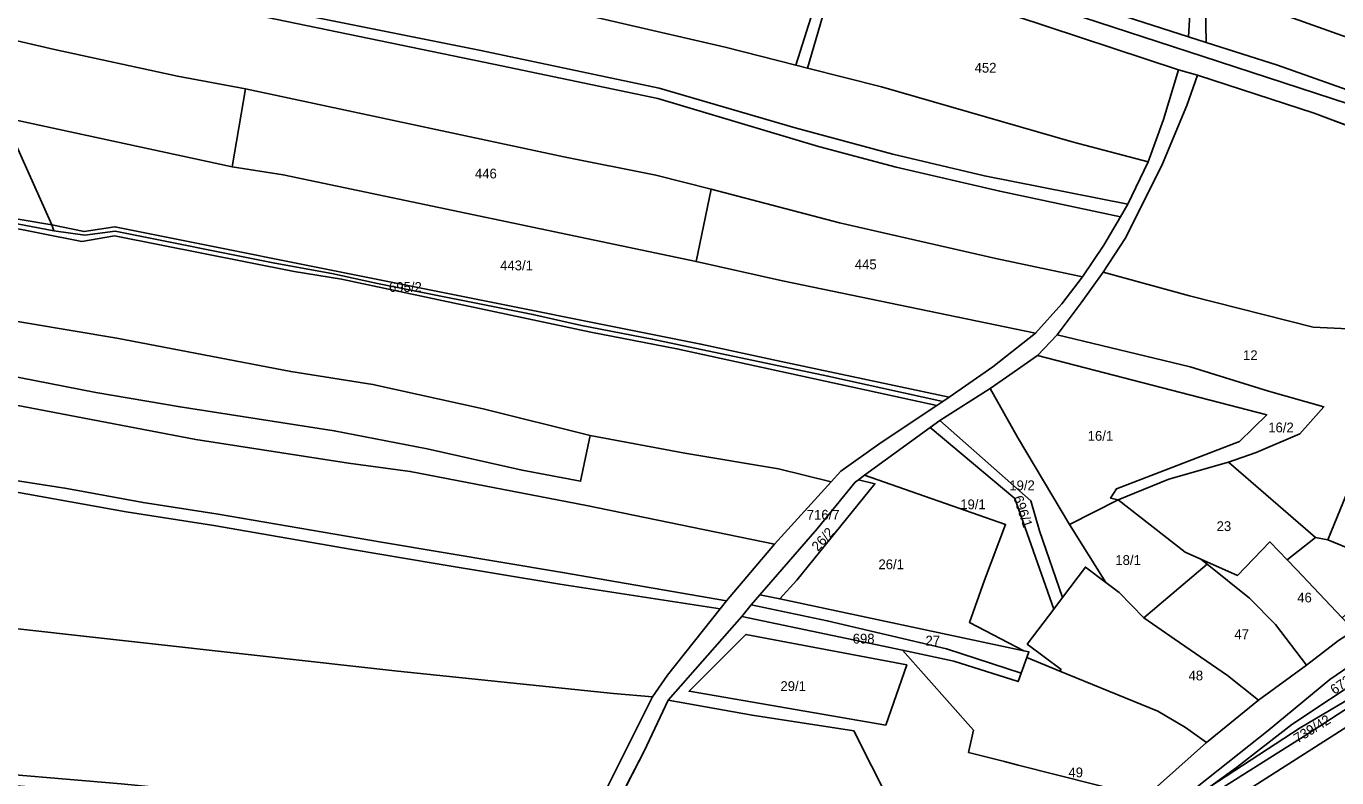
# Model space of a CAD drawing. Extents: x -629983 to -626385, y -1072828 to -1067897.
# Drawn here: x -627674 to -627272.2, y -1070260.1 to -1070029.7 of the extents above; entities that cross this region are included whole.
import ezdxf

# ---------------------------------------------------------------- set-up
doc = ezdxf.new("R2010")
doc.units = 0
for name, color, linetype in [('Parcela nároku', 7, 'Continuous'), ('Parcelní číslo', 7, 'Continuous'), ('Plocha PÚ', 7, 'Continuous'), ('silnice III třídy', 7, 'Continuous'), ('Vnitřní obvod_šetřený', 7, 'Continuous')]:
    doc.layers.add(name, color=color, linetype=linetype)

msp = doc.modelspace()

# ---------------------------------------------------------------- linework, layer by layer
at = {"layer": 'Parcela nároku'}
for points in [[(-627966.68, -1069918.48), (-627860.41, -1069943.87), (-627798.46, -1069959.34), (-627761.08, -1069969.25), (-627698.9, -1069984.16), (-627525.35, -1070020.94), (-627459.67, -1070036.19), (-627438.03, -1070041.67), (-627433.43, -1070027.14), (-627428.85, -1070009.96), (-627472.67, -1069998.76), (-627548.5, -1069979.01), (-627683.65, -1069947.01), (-627730.62, -1069934.75), (-627791.94, -1069919.96), (-627822.96, -1069911.43), (-627871.54, -1069899.35), (-627908.74, -1069890.74), (-627953.38, -1069880.27)], [(-627966.68, -1069918.48), (-627860.41, -1069943.87), (-627798.46, -1069959.34), (-627761.08, -1069969.25), (-627698.9, -1069984.16), (-627525.35, -1070020.94), (-627459.67, -1070036.19), (-627438.03, -1070041.67), (-627434.5, -1070042.56), (-627411.76, -1070048.32), (-627353.35, -1070065.17), (-627330, -1070071.29), (-627336.22, -1070084.29), (-627380.22, -1070075.61), (-627408.28, -1070068.97), (-627438.24, -1070060.91), (-627479.97, -1070048.75), (-627534.6, -1070037.2), (-627642.99, -1070015.46), (-627734.04, -1069994.19), (-627855.15, -1069966.75), (-627952.86, -1069945.56)], [(-627928.54, -1069954.07), (-627861.56, -1069968.14), (-627800, -1069981.82), (-627771, -1069988.66), (-627708.55, -1070002.4), (-627648.14, -1070016.64), (-627606.99, -1070025.62), (-627530.78, -1070041.4), (-627480.36, -1070051.91), (-627431.09, -1070066.57), (-627407.3, -1070072.95), (-627375.51, -1070080.32), (-627338.48, -1070088.13), (-627336.22, -1070084.29), (-627380.22, -1070075.61), (-627408.28, -1070068.97), (-627438.24, -1070060.91), (-627479.97, -1070048.75), (-627534.6, -1070037.2), (-627642.99, -1070015.46), (-627734.04, -1069994.19), (-627855.15, -1069966.75), (-627952.86, -1069945.56)], [(-627606.99, -1070025.62), (-627530.78, -1070041.4), (-627480.36, -1070051.91), (-627431.09, -1070066.57), (-627407.3, -1070072.95), (-627375.51, -1070080.32), (-627338.48, -1070088.13), (-627343.64, -1070096.86), (-627350.14, -1070106.49), (-627376.78, -1070100.94), (-627424.66, -1070089.97), (-627464, -1070079.68), (-627481.02, -1070075.36), (-627509.15, -1070069.78), (-627606.78, -1070048.94), (-627627.64, -1070045.09), (-627665.3, -1070036.87), (-627694.05, -1070030.28), (-627785.37, -1070010.96)], [(-627375.29, -1070014.41), (-627317.71, -1070033.01), (-627312.23, -1070034.74), (-627290.43, -1070041.64), (-627231.22, -1070062.6), (-627190.99, -1070076.44), (-627184.24, -1070074.01), (-627188.13, -1070087.13), (-627188.62, -1070095.15), (-627192.69, -1070087.86), (-627213.4, -1070080.48), (-627239.76, -1070070.47), (-627254.04, -1070065.86), (-627279.15, -1070056.4), (-627314.89, -1070044.76), (-627320.75, -1070043.1), (-627370.91, -1070026.56)], [(-627316.95, -1070020.66), (-627317.71, -1070033.01), (-627312.23, -1070034.74), (-627312.58, -1070017.57)], [(-627504.39, -1070279.94), (-627482.04, -1070235.24), (-627477.35, -1070228.63), (-627461.23, -1070208.23), (-627459.3, -1070205.79), (-627444.58, -1070188.48), (-627427.24, -1070169.35), (-627424.21, -1070166.04), (-627411.9, -1070157.27), (-627394.82, -1070145.92), (-627392.99, -1070144.7), (-627391.03, -1070143.4), (-627377.67, -1070134.13), (-627364.53, -1070123.84), (-627356.55, -1070114.81), (-627350.14, -1070106.49), (-627343.64, -1070096.86), (-627338.48, -1070088.13), (-627336.22, -1070084.29), (-627330, -1070071.29), (-627325.33, -1070058.33), (-627320.75, -1070043.1), (-627314.89, -1070044.76), (-627318.14, -1070054.02), (-627325.61, -1070071.91), (-627334.51, -1070089.76), (-627337.1, -1070094.84), (-627343.86, -1070105.11), (-627350.62, -1070114.47), (-627357.95, -1070124.32), (-627364.01, -1070130.61), (-627371.16, -1070135.67), (-627378.43, -1070140.75), (-627393.9, -1070150.54), (-627396.88, -1070152.67), (-627416.96, -1070167.33), (-627418.87, -1070168.72), (-627419.86, -1070169.44), (-627431.46, -1070183.72), (-627449.13, -1070203.94), (-627451.72, -1070207.04), (-627454.65, -1070210.58), (-627477.24, -1070236.31), (-627484.54, -1070251.9), (-627500.04, -1070281.83)], [(-627971.18, -1070066.38), (-627903.13, -1070079.86), (-627834.3, -1070092.45), (-627728.5, -1070111.57), (-627646.27, -1070125.36), (-627592.83, -1070135.55), (-627567.72, -1070139.52), (-627533.91, -1070146.95), (-627501.15, -1070155.18), (-627504.05, -1070169.16), (-627521.96, -1070165.82), (-627551.12, -1070159.2), (-627579.56, -1070153.71), (-627626.85, -1070146.42), (-627652.63, -1070141.94), (-627759.32, -1070121.18), (-627788.43, -1070116.53), (-627823.4, -1070110.05), (-627862.6, -1070105.05), (-627891.54, -1070100.28), (-627967.45, -1070086.39)], [(-627685.98, -1070088.51), (-627665.49, -1070092.47), (-627656, -1070093.79), (-627646.7, -1070092.56), (-627597.81, -1070102.39), (-627580.27, -1070105.56), (-627566.29, -1070108.55), (-627518.66, -1070118.04), (-627503.73, -1070121.43), (-627482.06, -1070125.59), (-627428.23, -1070136.95), (-627392.99, -1070144.7), (-627394.82, -1070145.92), (-627474.53, -1070128.57), (-627500.93, -1070123.45), (-627577.39, -1070107.21), (-627591.81, -1070104.87), (-627646.94, -1070093.99), (-627656.93, -1070095.7), (-627731.73, -1070080.89)], [(-627731.73, -1070080.89), (-627656.93, -1070095.7), (-627646.94, -1070093.99), (-627591.81, -1070104.87), (-627577.39, -1070107.21), (-627500.93, -1070123.45), (-627474.53, -1070128.57), (-627394.82, -1070145.92), (-627411.9, -1070157.27), (-627424.21, -1070166.04), (-627427.24, -1070169.35), (-627443.35, -1070165.39), (-627472.07, -1070160.59), (-627501.15, -1070155.18), (-627533.91, -1070146.95), (-627567.72, -1070139.52), (-627592.83, -1070135.55), (-627646.27, -1070125.36), (-627728.5, -1070111.57)], [(-627952.54, -1070097.03), (-627852.96, -1070114.78), (-627762.08, -1070129.98), (-627702.37, -1070141.02), (-627622, -1070156.42), (-627575.2, -1070163.69), (-627556.26, -1070166.16), (-627502.23, -1070176.65), (-627444.58, -1070188.48), (-627459.3, -1070205.79), (-627509.55, -1070197.12), (-627565.09, -1070187.83), (-627615.18, -1070179.27), (-627638.17, -1070175.73), (-627661.53, -1070171.41), (-627683.9, -1070167.96), (-627719.35, -1070161.23), (-627733.55, -1070159.56), (-627801.74, -1070148.45), (-627886.24, -1070137.46), (-627923.7, -1070133.29)], [(-627702.37, -1070141.02), (-627622, -1070156.42), (-627575.2, -1070163.69), (-627556.26, -1070166.16), (-627502.23, -1070176.65), (-627444.58, -1070188.48), (-627427.24, -1070169.35), (-627443.35, -1070165.39), (-627472.07, -1070160.59), (-627501.15, -1070155.18), (-627504.05, -1070169.16), (-627521.96, -1070165.82), (-627551.12, -1070159.2), (-627579.56, -1070153.71), (-627626.85, -1070146.42), (-627652.63, -1070141.94), (-627759.32, -1070121.18)], [(-627927.69, -1070135.69), (-627870.76, -1070142.6), (-627803.94, -1070151.81), (-627770.08, -1070156.67), (-627735.16, -1070162.49), (-627719.65, -1070164.52), (-627686.69, -1070170.82), (-627643.39, -1070178.51), (-627616.44, -1070182.76), (-627574.08, -1070190.13), (-627548.61, -1070194.42), (-627510.42, -1070200.71), (-627461.23, -1070208.23), (-627477.35, -1070228.63), (-627482.04, -1070235.24), (-627493.99, -1070234.25), (-627560.1, -1070227.33), (-627685.83, -1070213.41), (-627710.8, -1070210.1), (-627839.49, -1070195.32), (-627852.52, -1070193.73), (-627931.37, -1070179.87)], [(-627683.9, -1070167.96), (-627661.53, -1070171.41), (-627638.17, -1070175.73), (-627615.18, -1070179.27), (-627565.09, -1070187.83), (-627509.55, -1070197.12), (-627459.3, -1070205.79), (-627461.23, -1070208.23), (-627510.42, -1070200.71), (-627548.61, -1070194.42), (-627574.08, -1070190.13), (-627616.44, -1070182.76), (-627643.39, -1070178.51), (-627686.69, -1070170.82)], [(-628010.32, -1070222.78), (-627867.35, -1070243.48), (-627800.2, -1070247.16), (-627750.66, -1070252.06), (-627712.43, -1070256.17), (-627644.93, -1070261.86), (-627578.29, -1070268.4), (-627537.22, -1070274.1), (-627504.39, -1070279.94), (-627482.04, -1070235.24), (-627493.99, -1070234.25), (-627560.1, -1070227.33), (-627685.83, -1070213.41), (-627710.8, -1070210.1), (-627839.49, -1070195.32), (-627852.52, -1070193.73), (-627931.37, -1070179.87)], [(-627271.69, -1070218.01), (-627281.51, -1070225.51), (-627296.2, -1070236.27), (-627312.14, -1070249.25), (-627330.99, -1070266.01)], [(-627314.49, -1070262.38), (-627293.26, -1070245.57), (-627274.33, -1070229.94), (-627256.58, -1070217.73)], [(-627235.72, -1070217.21), (-627281.4, -1070246.83), (-627313.75, -1070267.23)], [(-628010.32, -1070222.78), (-627867.35, -1070243.48), (-627800.2, -1070247.16), (-627750.66, -1070252.06), (-627712.43, -1070256.17), (-627644.93, -1070261.86), (-627578.29, -1070268.4), (-627537.22, -1070274.1), (-627504.39, -1070279.94), (-627506.01, -1070282.58), (-627542.01, -1070276.06), (-627584.08, -1070270.83), (-627641.87, -1070265.31), (-627692.85, -1070261.34), (-627706.57, -1070260.22), (-627765.59, -1070253.53), (-627842.38, -1070247.97), (-627872.06, -1070246.99), (-627936.13, -1070236.87)], [(-627311.08, -1070262.87), (-627283.38, -1070244.72), (-627253.74, -1070227.22)], [(-627310.6, -1070270.86), (-627251.32, -1070233.14)]]:
    msp.add_lwpolyline(points, dxfattribs=at)
for points in [[(-627785.37, -1070010.96), (-627815.83, -1070004.37), (-627832.37, -1070000.14), (-627917.86, -1069981.38), (-627952.2, -1069973.99), (-627997.79, -1069964.89), (-628108.17, -1069942.02), (-628123.08, -1069937.86), (-628128.45, -1069964.26), (-628121.1, -1069966.23), (-628068.5, -1069978.38), (-628049.14, -1069982.94), (-627987.49, -1069993.82), (-627957.44, -1069999.19), (-627851.46, -1070020.69), (-627771.2, -1070038.21), (-627680.83, -1070057.74), (-627610.86, -1070072.86), (-627606.78, -1070048.94), (-627627.64, -1070045.09), (-627665.3, -1070036.87), (-627694.05, -1070030.28)], [(-627316.95, -1070020.66), (-627325.29, -1070018.57), (-627416.86, -1069989.64), (-627421.1, -1070001.12), (-627375.29, -1070014.41), (-627317.71, -1070033.01)], [(-627666.13, -1070090.61), (-627680.83, -1070057.74), (-627771.2, -1070038.21), (-627851.46, -1070020.69), (-627957.44, -1069999.19), (-627987.49, -1069993.82), (-627994.3, -1070025.41), (-627931.81, -1070038.01), (-627909.37, -1070043.13), (-627808.55, -1070062.26), (-627756.21, -1070072.57), (-627684.46, -1070087.52)], [(-627311.45, -1069996.38), (-627177.32, -1070047.82), (-627181.66, -1070064.26), (-627312.58, -1070017.57)], [(-627438.03, -1070041.67), (-627433.43, -1070027.14), (-627428.85, -1070009.96), (-627425.23, -1070011), (-627434.5, -1070042.56)], [(-627370.91, -1070026.56), (-627425.23, -1070011), (-627434.5, -1070042.56), (-627411.76, -1070048.32), (-627353.35, -1070065.17), (-627330, -1070071.29), (-627325.33, -1070058.33), (-627320.75, -1070043.1)], [(-627312.58, -1070017.57), (-627181.66, -1070064.26), (-627184.24, -1070074.01), (-627190.99, -1070076.44), (-627231.22, -1070062.6), (-627290.43, -1070041.64), (-627312.23, -1070034.74)], [(-627931.81, -1070038.01), (-627909.37, -1070043.13), (-627808.55, -1070062.26), (-627756.21, -1070072.57), (-627684.46, -1070087.52), (-627666.13, -1070090.61), (-627665.49, -1070092.47), (-627685.98, -1070088.51), (-627744.56, -1070076.52), (-627862.67, -1070053.18), (-627913.56, -1070043.43), (-627933.4, -1070039.04), (-627957.2, -1070034.43), (-627994.76, -1070026.71), (-627994.3, -1070025.41)], [(-627314.89, -1070044.76), (-627318.14, -1070054.02), (-627325.61, -1070071.91), (-627334.51, -1070089.76), (-627337.1, -1070094.84), (-627343.86, -1070105.11), (-627317.32, -1070112.34), (-627279.44, -1070121.96), (-627236.66, -1070124), (-627193.1, -1070132.19), (-627191.63, -1070121.34), (-627188.62, -1070095.15), (-627192.69, -1070087.86), (-627213.4, -1070080.48), (-627239.76, -1070070.47), (-627254.04, -1070065.86), (-627279.15, -1070056.4)], [(-627606.78, -1070048.94), (-627610.86, -1070072.86), (-627595.24, -1070075.25), (-627468.61, -1070101.85), (-627464, -1070079.68), (-627481.02, -1070075.36), (-627509.15, -1070069.78)], [(-627680.83, -1070057.74), (-627610.86, -1070072.86), (-627595.24, -1070075.25), (-627468.61, -1070101.85), (-627442.17, -1070107.72), (-627364.53, -1070123.84), (-627377.67, -1070134.13), (-627391.03, -1070143.4), (-627442.56, -1070132.48), (-627467.16, -1070127.17), (-627646.79, -1070091.19), (-627656.25, -1070092.65), (-627666.13, -1070090.61)], [(-627464, -1070079.68), (-627468.61, -1070101.85), (-627442.17, -1070107.72), (-627364.53, -1070123.84), (-627356.55, -1070114.81), (-627350.14, -1070106.49), (-627376.78, -1070100.94), (-627424.66, -1070089.97)], [(-627656.25, -1070092.65), (-627646.79, -1070091.19), (-627467.16, -1070127.17), (-627442.56, -1070132.48), (-627391.03, -1070143.4), (-627392.99, -1070144.7), (-627428.23, -1070136.95), (-627482.06, -1070125.59), (-627503.73, -1070121.43), (-627518.66, -1070118.04), (-627566.29, -1070108.55), (-627580.27, -1070105.56), (-627597.81, -1070102.39), (-627646.7, -1070092.56), (-627656, -1070093.79), (-627665.49, -1070092.47), (-627666.13, -1070090.61)], [(-627296.93, -1070160.37), (-627305.44, -1070163.31), (-627278.76, -1070186.43), (-627274.98, -1070187.17), (-627274.04, -1070184.86), (-627262.42, -1070156.4), (-627259, -1070147.64), (-627255.07, -1070137.59), (-627252.6, -1070138.69), (-627236.85, -1070125.26), (-627236.66, -1070124), (-627279.44, -1070121.96), (-627317.32, -1070112.34), (-627343.86, -1070105.11), (-627350.62, -1070114.47), (-627357.95, -1070124.32), (-627317.13, -1070134.11), (-627293.13, -1070141.6), (-627276.19, -1070146.37), (-627283.54, -1070154.63)], [(-627317.13, -1070134.11), (-627293.13, -1070141.6), (-627276.19, -1070146.37), (-627283.54, -1070154.63), (-627296.93, -1070160.37), (-627305.44, -1070163.31), (-627323.73, -1070168.59), (-627339.26, -1070174.84), (-627341.56, -1070174.33), (-627339.77, -1070171.47), (-627302, -1070157.01), (-627293.68, -1070148.85), (-627364.01, -1070130.61), (-627357.95, -1070124.32)], [(-627364.01, -1070130.61), (-627371.16, -1070135.67), (-627378.43, -1070140.75), (-627370.09, -1070155.72), (-627354.19, -1070182.4), (-627339.26, -1070174.84), (-627341.56, -1070174.33), (-627339.77, -1070171.47), (-627302, -1070157.01), (-627293.68, -1070148.85)], [(-627255.07, -1070137.59), (-627252.6, -1070138.69), (-627221.42, -1070152.62), (-627228.91, -1070171.82), (-627231.22, -1070177.74), (-627220.97, -1070181.74), (-627221.7, -1070183.6), (-627231.95, -1070179.6), (-627238.98, -1070176.84), (-627244.17, -1070189.75), (-627245.87, -1070194.19), (-627251.86, -1070192.91), (-627255.8, -1070199.77), (-627258.15, -1070197.92), (-627269.24, -1070189.51), (-627274.98, -1070187.17), (-627274.04, -1070184.86), (-627262.42, -1070156.4), (-627259, -1070147.64)], [(-627378.43, -1070140.75), (-627393.9, -1070150.54), (-627366.05, -1070175.15), (-627363.36, -1070184.4), (-627356.26, -1070204.85), (-627349.25, -1070195.46), (-627342.99, -1070200.19), (-627354.19, -1070182.4), (-627370.09, -1070155.72)], [(-627393.9, -1070150.54), (-627396.88, -1070152.67), (-627370.92, -1070174.51), (-627358.94, -1070208.42), (-627356.26, -1070204.85), (-627363.36, -1070184.4), (-627366.05, -1070175.15)], [(-627367.09, -1070219.08), (-627356.72, -1070226.92), (-627357.1, -1070227.42), (-627367.23, -1070223.22), (-627366.59, -1070221.43), (-627368.11, -1070221.11), (-627384.83, -1070212.44), (-627380.2, -1070199.52), (-627373.76, -1070182.44), (-627416.96, -1070167.33), (-627396.88, -1070152.67), (-627370.92, -1070174.51), (-627358.94, -1070208.42)], [(-627323.73, -1070168.59), (-627305.44, -1070163.31), (-627278.76, -1070186.43), (-627287.43, -1070193.23), (-627289.93, -1070190.6), (-627292.76, -1070187.76), (-627302.61, -1070198.02), (-627313.87, -1070193.05), (-627318.69, -1070190.93), (-627339.26, -1070174.84)], [(-627413.82, -1070169.97), (-627437.7, -1070199.49), (-627442.99, -1070205.24), (-627368.11, -1070221.11), (-627384.83, -1070212.44), (-627380.2, -1070199.52), (-627373.76, -1070182.44), (-627416.96, -1070167.33), (-627418.87, -1070168.72)], [(-627419.86, -1070169.44), (-627431.46, -1070183.72), (-627449.13, -1070203.94), (-627442.99, -1070205.24), (-627437.7, -1070199.49), (-627413.82, -1070169.97), (-627418.87, -1070168.72)], [(-627354.19, -1070182.4), (-627339.26, -1070174.84), (-627318.69, -1070190.93), (-627313.87, -1070193.05), (-627311.94, -1070194.6), (-627331.39, -1070210.99), (-627338.88, -1070203.3), (-627342.99, -1070200.19)], [(-627270.58, -1070211), (-627266.87, -1070214.91), (-627271.69, -1070218.01), (-627281.51, -1070225.51), (-627291.04, -1070213.07), (-627299.01, -1070205), (-627311.94, -1070194.6), (-627313.87, -1070193.05), (-627302.61, -1070198.02), (-627292.76, -1070187.76), (-627289.93, -1070190.6), (-627287.43, -1070193.23), (-627284.56, -1070196.26)], [(-627274.98, -1070187.17), (-627269.24, -1070189.51), (-627258.15, -1070197.92), (-627255.8, -1070199.77), (-627250.55, -1070203.9), (-627263.76, -1070212.92), (-627267.65, -1070208.53), (-627270.58, -1070211), (-627284.56, -1070196.26), (-627287.43, -1070193.23), (-627278.76, -1070186.43)], [(-627356.26, -1070204.85), (-627349.25, -1070195.46), (-627342.99, -1070200.19), (-627338.88, -1070203.3), (-627331.39, -1070210.99), (-627322.05, -1070217.45), (-627305.74, -1070228.74), (-627296.2, -1070236.27), (-627312.14, -1070249.25), (-627318.56, -1070244.65), (-627327.06, -1070239.59), (-627357.1, -1070227.42), (-627356.72, -1070226.92), (-627367.09, -1070219.08), (-627358.94, -1070208.42)], [(-627291.04, -1070213.07), (-627281.51, -1070225.51), (-627296.2, -1070236.27), (-627305.74, -1070228.74), (-627322.05, -1070217.45), (-627331.39, -1070210.99), (-627311.94, -1070194.6), (-627299.01, -1070205)], [(-627368.11, -1070221.11), (-627366.59, -1070221.43), (-627367.23, -1070223.22), (-627368.92, -1070227.99), (-627391.81, -1070220.56), (-627428.41, -1070211.93), (-627451.72, -1070207.04), (-627449.13, -1070203.94), (-627442.99, -1070205.24)], [(-627274.33, -1070229.94), (-627293.26, -1070245.57), (-627314.49, -1070262.38), (-627324.47, -1070271.16), (-627311.08, -1070262.87), (-627302.99, -1070256.91), (-627285.94, -1070243.76), (-627262.58, -1070228.21), (-627241.08, -1070214.74), (-627233.73, -1070210.98), (-627219.25, -1070207.1), (-627223.95, -1070202.72), (-627229.52, -1070202.24), (-627256.58, -1070217.73)], [(-627451.72, -1070207.04), (-627428.41, -1070211.93), (-627391.81, -1070220.56), (-627368.92, -1070227.99), (-627369.93, -1070230.55), (-627389.65, -1070224.29), (-627405.34, -1070220.98), (-627454.65, -1070210.58)], [(-627281.4, -1070246.83), (-627235.72, -1070217.21), (-627221.49, -1070213.01), (-627179.8, -1070206.02), (-627218.8, -1070213.83), (-627232.77, -1070222.84), (-627237.4, -1070226.24), (-627249.09, -1070231.35), (-627251.32, -1070233.14), (-627310.6, -1070270.86), (-627313.75, -1070267.23)], [(-627285.94, -1070243.76), (-627302.99, -1070256.91), (-627311.08, -1070262.87), (-627283.38, -1070244.72), (-627253.74, -1070227.22), (-627230.57, -1070214.05), (-627219.25, -1070207.1), (-627233.73, -1070210.98), (-627241.08, -1070214.74), (-627262.58, -1070228.21)], [(-627369.9, -1070256.15), (-627334.23, -1070265.22), (-627330.99, -1070266.01), (-627349.67, -1070277.25), (-627359.4, -1070288.74), (-627364.81, -1070286.4), (-627383.81, -1070278.2), (-627409.42, -1070267.15), (-627420.23, -1070245.71), (-627451.48, -1070240.87), (-627477.24, -1070236.31), (-627454.65, -1070210.58), (-627405.34, -1070220.98), (-627383.62, -1070245.45), (-627385.11, -1070252.28), (-627374.12, -1070255.08)], [(-627453.35, -1070216.1), (-627470.8, -1070233.52), (-627410.46, -1070243.89), (-627404.03, -1070225.41)], [(-627470.8, -1070233.52), (-627410.46, -1070243.89), (-627404.03, -1070225.41), (-627453.35, -1070216.1)], [(-627327.06, -1070239.59), (-627318.56, -1070244.65), (-627312.14, -1070249.25), (-627330.99, -1070266.01), (-627334.23, -1070265.22), (-627369.9, -1070256.15), (-627374.12, -1070255.08), (-627385.11, -1070252.28), (-627383.62, -1070245.45), (-627405.34, -1070220.98), (-627389.65, -1070224.29), (-627369.93, -1070230.55), (-627368.92, -1070227.99), (-627367.23, -1070223.22), (-627357.1, -1070227.42)], [(-627477.24, -1070236.31), (-627484.54, -1070251.9), (-627500.04, -1070281.83), (-627475.57, -1070284), (-627464.35, -1070285.62), (-627429.37, -1070289.04), (-627418.41, -1070263.38), (-627409.42, -1070267.15), (-627420.23, -1070245.71), (-627451.48, -1070240.87)]]:
    msp.add_lwpolyline(points, close=True, dxfattribs=at)
at = {"layer": 'Plocha PÚ'}
for points in [[(-627343.86, -1070105.11), (-627337.1, -1070094.84), (-627325.61, -1070071.91), (-627318.14, -1070054.02), (-627314.89, -1070044.76), (-627279.15, -1070056.4), (-627266.6, -1070061.13)], [(-627454.65, -1070210.58), (-627451.72, -1070207.04), (-627449.13, -1070203.94), (-627431.46, -1070183.72), (-627419.86, -1070169.44), (-627418.87, -1070168.72), (-627416.96, -1070167.33), (-627396.88, -1070152.67), (-627393.9, -1070150.54), (-627378.43, -1070140.75), (-627371.16, -1070135.67), (-627364.01, -1070130.61), (-627357.95, -1070124.32), (-627350.62, -1070114.47), (-627343.86, -1070105.11)], [(-627500.04, -1070281.83), (-627484.54, -1070251.9), (-627477.24, -1070236.31), (-627454.65, -1070210.58)]]:
    msp.add_lwpolyline(points, dxfattribs=at)
at = {"layer": 'silnice III třídy'}
msp.add_lwpolyline([(-627179.13, -1070085.76), (-627198.03, -1070077.93), (-627215.91, -1070071.53), (-627241.19, -1070062.48), (-627273.72, -1070051.86), (-627313.17, -1070038.98), (-627368.35, -1070020.97), (-627428.11, -1070004.67), (-627469.26, -1069994.36), (-627510.41, -1069984.05), (-627563.5, -1069970.75), (-627602.12, -1069962.61), (-627657.83, -1069948.79), (-627708.45, -1069937.73), (-627718.05, -1069933.95), (-627728.23, -1069927.84), (-627736.09, -1069919.69), (-627744.96, -1069902.23), (-627755.43, -1069876.77)], dxfattribs=at)
at = {"layer": 'Vnitřní obvod_šetřený'}
for p, q in [((-627318.14, -1070054.02), (-627314.89, -1070044.76)), ((-627314.89, -1070044.76), (-627279.15, -1070056.4)), ((-627325.61, -1070071.91), (-627318.14, -1070054.02)), ((-627279.15, -1070056.4), (-627254.04, -1070065.86)), ((-627337.1, -1070094.84), (-627325.61, -1070071.91)), ((-627343.86, -1070105.11), (-627337.1, -1070094.84)), ((-627350.62, -1070114.47), (-627343.86, -1070105.11)), ((-627357.95, -1070124.32), (-627350.62, -1070114.47)), ((-627364.01, -1070130.61), (-627357.95, -1070124.32)), ((-627371.16, -1070135.67), (-627364.01, -1070130.61)), ((-627378.43, -1070140.75), (-627371.16, -1070135.67)), ((-627393.9, -1070150.54), (-627378.43, -1070140.75)), ((-627396.88, -1070152.67), (-627393.9, -1070150.54)), ((-627416.96, -1070167.33), (-627396.88, -1070152.67)), ((-627418.87, -1070168.72), (-627416.96, -1070167.33)), ((-627431.46, -1070183.72), (-627419.86, -1070169.44)), ((-627419.86, -1070169.44), (-627418.87, -1070168.72)), ((-627449.13, -1070203.94), (-627431.46, -1070183.72)), ((-627451.72, -1070207.04), (-627449.13, -1070203.94)), ((-627454.65, -1070210.58), (-627451.72, -1070207.04)), ((-627477.24, -1070236.31), (-627454.65, -1070210.58)), ((-627484.54, -1070251.9), (-627477.24, -1070236.31)), ((-627500.04, -1070281.83), (-627484.54, -1070251.9))]:
    msp.add_line(p, q, dxfattribs=at)

# ---------------------------------------------------------------- texts
at = {"layer": 'Parcelní číslo'}
for s, p in [('452', (-627383.24, -1070043.96)), ('446', (-627536.43, -1070076.39)), ('443/1', (-627528.7, -1070104.55)), ('445', (-627419.96, -1070104.22)), ('695/2', (-627562.76, -1070111.15)), ('12', (-627300.95, -1070132.06)), ('16/2', (-627293.21, -1070154.2)), ('16/1', (-627348.57, -1070156.77)), ('19/2', (-627372.6, -1070171.94)), ('19/1', (-627387.64, -1070177.75)), ('716/7', (-627434.69, -1070180.95)), ('23', (-627309.04, -1070184.44)), ('18/1', (-627340.09, -1070194.83)), ('26/1', (-627412.72, -1070196.14)), ('46', (-627284.32, -1070206.32)), ('698', (-627420.61, -1070218.92)), ('27', (-627398.29, -1070219.52)), ('47', (-627303.59, -1070217.58)), ('48', (-627317.65, -1070230.21)), ('29/1', (-627442.77, -1070233.46)), ('49', (-627354.47, -1070259.91))]:
    msp.add_text(s, height=3, dxfattribs=at).set_placement(p)
for s, rotation, p in [('696/1', 288.3767, (-627371.4, -1070174.15)), ('26/2', 48.1935, (-627431.28, -1070190.85)), ('672/1', 34.6016, (-627272.9, -1070234.67)), ('739/42', 31.6044, (-627284.23, -1070249.54))]:
    msp.add_text(s, height=3, rotation=rotation, dxfattribs=at).set_placement(p)

doc.saveas('drawing.dxf')
